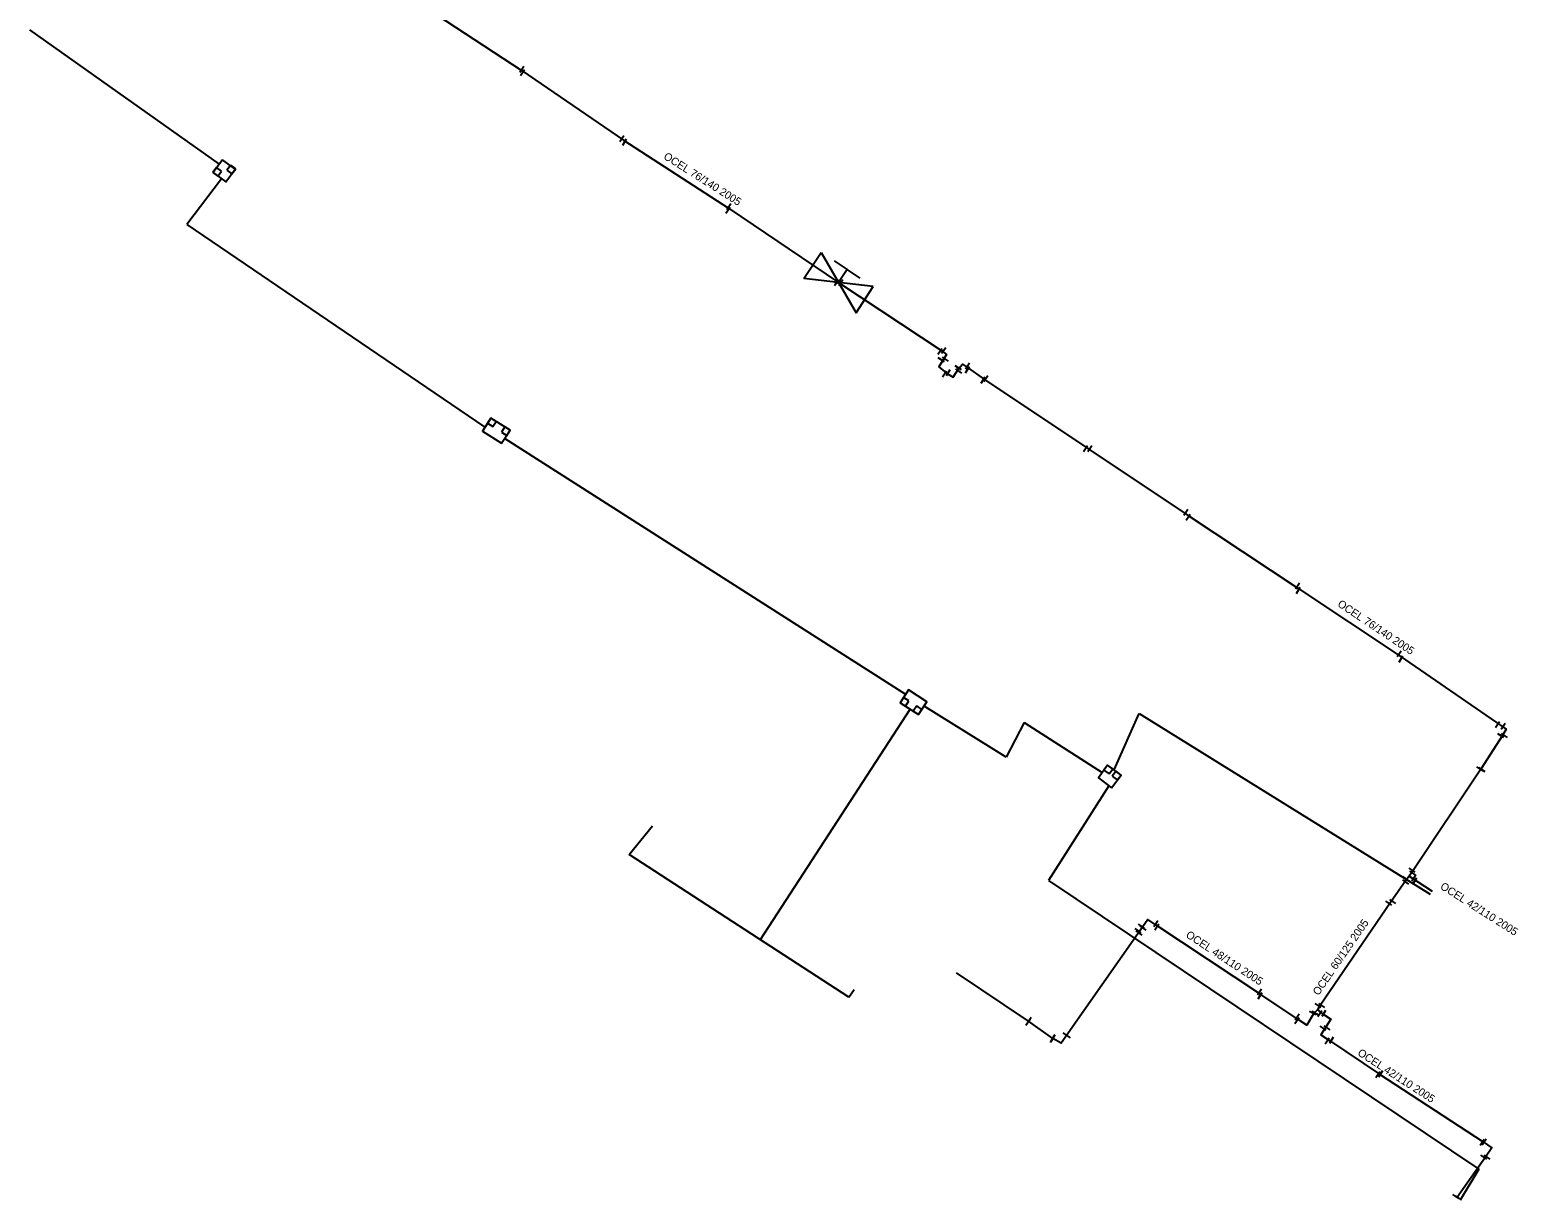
# Model space of a CAD drawing. Extents: x -642943 to -623314, y -1138561 to -1113539.
# Drawn here: x -641898.8 to -641755.6, y -1115757.5 to -1115644.8 of the extents above; entities that cross this region are included whole.
import ezdxf

# ---------------------------------------------------------------- set-up
doc = ezdxf.new("R2010")
doc.units = 0
for name, color, linetype in [('horkovod armatury', 7, 'Continuous'), ('horkovod dimenze', 7, 'Continuous'), ('horkovod předisol', 7, 'Continuous'), ('horkovod sváry', 7, 'Continuous'), ('horkovod trasa', 7, 'Continuous'), ('horkovod zrušený', 7, 'Continuous')]:
    doc.layers.add(name, color=color, linetype=linetype)

# ---------------------------------------------------------------- blocks, each defined once
blk = doc.blocks.new('POINT_DISPLAY')
blk.add_line((0, 0), (0, 0))
blk = doc.blocks.new('SPH')
at = {"layer": 'horkovod sváry'}
blk.add_line((0, -0.035), (0, 0.035), dxfattribs=at)
blk = doc.blocks.new('SCH_01_109')
at = {"layer": 'horkovod armatury'}
for p, q in [((10, 5), (-10, -5)), ((-10, -5), (-10, 5)), ((-10, 5), (10, -5)), ((-5, 5), (0, 5)), ((0, 5), (0, 0)), ((5, 5), (0, 5)), ((10, -5), (10, 5))]:
    blk.add_line(p, q, dxfattribs=at)

msp = doc.modelspace()

# ---------------------------------------------------------------- linework, layer by layer
at = {"layer": 'horkovod armatury'}
for centre in [(-641821.23, -1115669.14), (-641820.81, -1115669.13)]:
    msp.add_circle(centre, 0.1, dxfattribs=at)
at = {"layer": 'horkovod předisol'}
msp.add_line((-641766.14, -1115726.28), (-641763.92, -1115727.71), dxfattribs=at)
for points in [[(-641861.61, -1115642.13), (-641851.47, -1115648.76), (-641841.74, -1115655.44), (-641831.64, -1115661.98), (-641821.03, -1115669.13), (-641811.09, -1115675.72), (-641810.64, -1115676.08), (-641811.4, -1115677.26), (-641810.64, -1115677.87), (-641810.02, -1115678.26), (-641809.49, -1115677.46), (-641809.12, -1115677), (-641808.64, -1115677.33), (-641806.99, -1115678.46), (-641797.06, -1115685.12), (-641787.48, -1115691.5), (-641776.84, -1115698.54), (-641767.01, -1115705.11), (-641756.81, -1115712.13), (-641757.16, -1115712.74), (-641759.23, -1115715.98), (-641765.81, -1115725.84), (-641766.14, -1115726.28)], [(-641766.14, -1115726.28), (-641766.45, -1115726.68), (-641767.92, -1115728.82), (-641774.7, -1115738.71), (-641774.97, -1115739.14)], [(-641774.97, -1115739.14), (-641775.3, -1115739.47), (-641775.99, -1115740.62), (-641776.91, -1115740), (-641780.5, -1115737.6), (-641790.48, -1115730.99), (-641791.27, -1115730.45), (-641791.8, -1115731.18), (-641799.61, -1115742.36), (-641800.42, -1115741.89), (-641802.77, -1115740.22), (-641809.7, -1115735.57)], [(-641774.97, -1115739.14), (-641774.5, -1115739.49), (-641773.67, -1115740.05), (-641774.63, -1115741.54), (-641773.81, -1115742.08), (-641768.99, -1115745.33), (-641759.01, -1115751.86), (-641758.18, -1115752.44), (-641758.79, -1115753.32), (-641761.56, -1115757.24)]]:
    msp.add_lwpolyline(points, dxfattribs=at)
at = {"layer": 'horkovod trasa'}
msp.add_line((-641766.14, -1115726.28), (-641763.92, -1115727.71), dxfattribs=at)
for points in [[(-641861.61, -1115642.13), (-641851.47, -1115648.76), (-641841.74, -1115655.44), (-641831.64, -1115661.98), (-641821.03, -1115669.13), (-641811.09, -1115675.72), (-641810.64, -1115676.08), (-641811.4, -1115677.26), (-641810.64, -1115677.87), (-641810.02, -1115678.26), (-641809.49, -1115677.46), (-641809.12, -1115677), (-641808.64, -1115677.33), (-641806.99, -1115678.46), (-641797.06, -1115685.12), (-641787.48, -1115691.5), (-641776.84, -1115698.54), (-641767.01, -1115705.11), (-641756.81, -1115712.13), (-641757.16, -1115712.74), (-641759.23, -1115715.98), (-641765.81, -1115725.84), (-641766.14, -1115726.28)], [(-641766.14, -1115726.28), (-641766.45, -1115726.68), (-641767.92, -1115728.82), (-641774.7, -1115738.71), (-641774.97, -1115739.14)], [(-641774.97, -1115739.14), (-641775.3, -1115739.47), (-641775.99, -1115740.62), (-641776.91, -1115740), (-641780.5, -1115737.6), (-641790.48, -1115730.99), (-641791.27, -1115730.45), (-641791.8, -1115731.18), (-641799.61, -1115742.36), (-641800.42, -1115741.89), (-641802.77, -1115740.22), (-641809.7, -1115735.57)], [(-641774.97, -1115739.14), (-641774.5, -1115739.49), (-641773.67, -1115740.05), (-641774.63, -1115741.54), (-641773.81, -1115742.08), (-641768.99, -1115745.33), (-641759.01, -1115751.86), (-641758.18, -1115752.44), (-641758.79, -1115753.32), (-641761.56, -1115757.24)]]:
    msp.add_lwpolyline(points, dxfattribs=at)
at = {"layer": 'horkovod zrušený'}
for p, q in [((-641880.6, -1115657.73), (-641898.85, -1115644.81)), ((-641880.87, -1115658.07), (-641881.23, -1115658.55)), ((-641880.39, -1115658.43), (-641880.87, -1115658.07)), ((-641879.52, -1115657.85), (-641879.88, -1115658.33)), ((-641879.04, -1115658.21), (-641879.52, -1115657.85)), ((-641879.4, -1115658.69), (-641879.04, -1115658.21)), ((-641880.39, -1115659.15), (-641883.75, -1115663.55)), ((-641881.23, -1115658.55), (-641880.75, -1115658.91)), ((-641880.75, -1115658.91), (-641880.39, -1115658.43)), ((-641879.88, -1115658.33), (-641879.4, -1115658.69)), ((-641883.75, -1115663.55), (-641855.06, -1115683.07)), ((-641854.49, -1115682.19), (-641854.81, -1115682.69)), ((-641853.99, -1115682.51), (-641854.49, -1115682.19)), ((-641854.31, -1115683.01), (-641853.99, -1115682.51)), ((-641854.81, -1115682.69), (-641854.31, -1115683.01)), ((-641853.13, -1115683.03), (-641853.46, -1115683.53)), ((-641853.46, -1115683.53), (-641852.96, -1115683.86)), ((-641852.63, -1115683.36), (-641853.13, -1115683.03)), ((-641852.96, -1115683.86), (-641852.63, -1115683.36)), ((-641853.15, -1115684.15), (-641814.58, -1115708.77)), ((-641814.78, -1115709.08), (-641815.1, -1115709.58)), ((-641815.1, -1115709.58), (-641814.6, -1115709.9)), ((-641814.28, -1115709.4), (-641814.78, -1115709.08)), ((-641814.6, -1115709.9), (-641814.28, -1115709.4)), ((-641828.55, -1115732.36), (-641814.16, -1115710.19)), ((-641813.51, -1115709.88), (-641813.85, -1115710.38)), ((-641813.85, -1115710.38), (-641813.35, -1115710.72)), ((-641813.01, -1115710.22), (-641813.51, -1115709.88)), ((-641813.35, -1115710.72), (-641813.01, -1115710.22)), ((-641804.92, -1115714.83), (-641812.8, -1115709.92)), ((-641794.52, -1115716.05), (-641792.12, -1115710.63)), ((-641792.12, -1115710.63), (-641764.11, -1115728.01)), ((-641803.17, -1115711.47), (-641804.92, -1115714.83)), ((-641803.17, -1115711.47), (-641795.66, -1115716.29)), ((-641795.15, -1115715.58), (-641795.5, -1115716.07)), ((-641794.66, -1115715.93), (-641795.15, -1115715.58)), ((-641795.5, -1115716.07), (-641795.01, -1115716.42)), ((-641795.01, -1115716.42), (-641794.66, -1115715.93)), ((-641794.34, -1115716.18), (-641794.7, -1115716.66)), ((-641794.7, -1115716.66), (-641794.22, -1115717.02)), ((-641793.86, -1115716.54), (-641794.34, -1115716.18)), ((-641794.22, -1115717.02), (-641793.86, -1115716.54)), ((-641795.02, -1115717.57), (-641800.85, -1115726.7)), ((-641841.18, -1115724.18), (-641838.94, -1115721.43)), ((-641820.06, -1115737.92), (-641841.18, -1115724.18)), ((-641800.85, -1115726.7), (-641759.44, -1115754.47)), ((-641820.06, -1115737.92), (-641819.55, -1115737.17)), ((-641759.44, -1115754.47), (-641761.23, -1115757.47))]:
    msp.add_line(p, q, dxfattribs=at)
for points in [[(-641880.3, -1115657.32), (-641881.2, -1115658.54), (-641879.98, -1115659.44), (-641879.08, -1115658.22), (-641880.3, -1115657.32)], [(-641853.45, -1115684.61), (-641852.63, -1115683.36), (-641854.49, -1115682.19), (-641855.3, -1115683.45), (-641853.45, -1115684.61)], [(-641813.35, -1115710.72), (-641812.53, -1115709.5), (-641814.31, -1115708.34), (-641815.1, -1115709.58), (-641813.35, -1115710.72)], [(-641794.76, -1115717.76), (-641793.86, -1115716.54), (-641795.15, -1115715.58), (-641796.03, -1115716.82), (-641794.76, -1115717.76)]]:
    msp.add_lwpolyline(points, dxfattribs=at)

# ---------------------------------------------------------------- block references
at = {"layer": 'horkovod armatury', "xscale": 0.29998715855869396, "yscale": 0.29998715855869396, "rotation": -33.22654402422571}
msp.add_blockref('SCH_01_109', (-641821.03, -1115669.14), dxfattribs=at)
at = {"layer": 'horkovod sváry'}
for p, xscale, yscale, rotation in [((-641851.51, -1115648.59), 10.000007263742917, 10.000007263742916, -33.51809530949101), ((-641851.45, -1115648.91), 10.00001724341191, 10.00001724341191, -33.85634168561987), ((-641841.89, -1115655.27), 10.00001054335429, 10.000010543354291, -32.200241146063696), ((-641841.61, -1115655.61), 9.99998342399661, 9.999983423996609, -32.147383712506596), ((-641831.67, -1115662.18), 9.999983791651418, 9.99998379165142, -34.07715628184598), ((-641831.59, -1115661.81), 10.000012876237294, 10.000012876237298, -35.38539210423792), ((-641821.24, -1115669.14), 10.000012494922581, 10.00001249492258, -34.52339088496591), ((-641820.82, -1115669.14), 9.999999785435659, 9.999999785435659, -33.359219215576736), ((-641811.27, -1115675.75), 10.000007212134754, 10.000007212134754, -38.17553854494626), ((-641810.92, -1115675.66), 10.000021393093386, 10.000021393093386, -37.53478850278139), ((-641811.15, -1115676.58), 9.99999480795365, 9.999994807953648, 57.46201646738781), ((-641810.74, -1115676.51), 9.999986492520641, 9.999986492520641, 56.18369107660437), ((-641808.64, -1115677.16), 10.000012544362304, 10.000012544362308, -33.931894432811), ((-641810.84, -1115677.92), 10.000023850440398, 10.000023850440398, -32.943257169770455), ((-641810.47, -1115677.8), 9.999988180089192, 9.999988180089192, -32.02990307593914), ((-641809.54, -1115677.31), 9.999987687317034, 9.999987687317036, -122.76933973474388), ((-641809.49, -1115677.65), 10.000005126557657, 10.000005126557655, -124.15344978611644), ((-641808.63, -1115677.52), 9.999999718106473, 9.999999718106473, -32.55885576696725), ((-641807.13, -1115678.52), 10.000016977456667, 10.000016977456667, -33.998789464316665), ((-641806.88, -1115678.38), 9.999996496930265, 9.999996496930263, -33.47110590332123), ((-641797.27, -1115685.12), 10.000029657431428, 10.000029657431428, -33.31918648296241), ((-641796.87, -1115685.12), 10.000002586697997, 10.000002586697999, -33.65743427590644), ((-641787.63, -1115691.25), 9.999989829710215, 9.999989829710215, -33.65588026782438), ((-641787.41, -1115691.72), 9.99999135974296, 9.999991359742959, -32.31104860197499), ((-641776.88, -1115698.32), 9.999999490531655, 9.999999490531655, -34.73549977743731), ((-641776.8, -1115698.76), 10.000017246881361, 10.00001724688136, -32.75431885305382), ((-641767.1, -1115704.86), 9.999986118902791, 9.999986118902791, -35.101286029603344), ((-641766.92, -1115705.38), 10.00001880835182, 10.000018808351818, -32.22133888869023), ((-641757.65, -1115711.67), 9.999995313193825, 9.999995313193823, -33.83747240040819), ((-641757.32, -1115712.75), 10.000006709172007, 10.000006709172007, 58.872754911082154), ((-641757.09, -1115711.84), 10.000030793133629, 10.000030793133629, -34.134652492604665), ((-641756.97, -1115712.73), 10.0000124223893, 10.0000124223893, 56.84598341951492), ((-641759.34, -1115715.94), 10.000010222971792, 10.000010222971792, 58.521474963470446), ((-641759.13, -1115716.04), 10.000013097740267, 10.000013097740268, 56.81379283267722), ((-641765.85, -1115725.7), 9.9999780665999, 9.9999780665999, 58.05530848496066), ((-641766.46, -1115726.52), 10.000013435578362, 10.000013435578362, 55.83175045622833), ((-641766.45, -1115726.84), 10.000012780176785, 10.000012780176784, 56.182507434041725), ((-641765.78, -1115725.99), 9.999988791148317, 9.999988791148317, 56.61613930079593), ((-641765.7, -1115726.43), 9.999999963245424, 9.999999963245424, -32.72900634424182), ((-641765.6, -1115726.74), 10.000012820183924, 10.000012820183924, -33.40006726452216), ((-641768.09, -1115728.88), 10.000000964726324, 10.000000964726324, 56.30985847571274), ((-641767.72, -1115728.71), 9.999984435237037, 9.999984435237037, 55.8429232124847), ((-641792.21, -1115731.52), 9.999978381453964, 9.999978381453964, 54.246112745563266), ((-641791.88, -1115731.08), 10.000023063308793, 10.000023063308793, 56.509801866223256), ((-641791.74, -1115731.27), 10.000007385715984, 10.000007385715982, 55.22231473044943), ((-641790.52, -1115730.84), 9.999986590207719, 9.999986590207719, -33.603341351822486), ((-641790.41, -1115731.15), 9.999977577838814, 9.999977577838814, -33.15956483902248), ((-641792.11, -1115731.76), 9.999995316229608, 9.999995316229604, 53.69125527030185), ((-641780.54, -1115737.41), 10.000000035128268, 10.000000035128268, -34.04585370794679), ((-641780.48, -1115737.78), 10.000000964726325, 10.000000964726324, -33.6901415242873), ((-641802.7, -1115740.15), 9.999975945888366, 9.999975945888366, -34.97619533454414), ((-641776.93, -1115740.18), 10.00001058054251, 10.00001058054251, -34.157297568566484), ((-641776.92, -1115739.81), 10.000002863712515, 10.000002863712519, -33.98339804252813), ((-641775.43, -1115739.47), 9.99997188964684, 9.99997188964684, 61.2573295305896), ((-641775.2, -1115739.45), 10.000009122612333, 10.000009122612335, -119.71079548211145), ((-641774.88, -1115738.73), 9.999980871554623, 9.999980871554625, 55.7935642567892), ((-641774.72, -1115739.5), 9.999970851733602, 9.999970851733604, -34.04274674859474), ((-641774.54, -1115738.73), 10.000023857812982, 10.00002385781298, 55.81598878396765), ((-641774.34, -1115739.46), 9.999991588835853, 9.999991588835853, -31.281080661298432), ((-641802.81, -1115740.32), 10.000009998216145, 10.000009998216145, -35.797494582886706), ((-641799.13, -1115741.54), 9.999991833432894, 9.999991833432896, 55.55453517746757), ((-641774.41, -1115740.91), 10.00000104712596, 10.000001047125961, 56.920800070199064), ((-641774.03, -1115740.87), 9.999986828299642, 9.999986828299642, 55.14911396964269), ((-641800.47, -1115741.97), 9.999988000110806, 9.999988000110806, -27.614519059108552), ((-641800.37, -1115741.82), 10.000021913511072, 10.000021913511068, -28.072455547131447), ((-641799.01, -1115741.65), 9.999985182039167, 9.999985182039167, 55.45706913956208), ((-641774.02, -1115742.13), 10.000003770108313, 10.000003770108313, -34.15248783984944), ((-641773.6, -1115742.04), 10.000003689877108, 10.000003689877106, -30.74993537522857), ((-641769.14, -1115745.37), 10.000008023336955, 10.000008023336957, -32.775928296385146), ((-641768.86, -1115745.29), 9.999983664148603, 9.999983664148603, -31.94121294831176), ((-641759.11, -1115751.88), 10.000008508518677, 10.000008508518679, -34.556768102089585), ((-641758.93, -1115751.84), 10.000005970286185, 10.000005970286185, -34.55580623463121), ((-641758.95, -1115753.32), 9.999980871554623, 9.999980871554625, 55.7935642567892), ((-641758.64, -1115753.32), 9.999993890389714, 9.999993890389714, 54.92417808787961), ((-641761.65, -1115757.11), 10.000005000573, 10.000005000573, 54.566782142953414), ((-641761.4, -1115757.24), 10.000005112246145, 10.000005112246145, 55.24666420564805)]:
    msp.add_blockref('SPH', p, dxfattribs=dict(at, xscale=xscale, yscale=yscale, rotation=rotation))
at = {"layer": 'horkovod zrušený'}
for p in [(-641879.46, -1115658.27), (-641880.81, -1115658.49), (-641854.4, -1115682.6), (-641853.04, -1115683.44), (-641814.69, -1115709.49), (-641813.43, -1115710.3), (-641813.43, -1115710.3), (-641795.08, -1115716), (-641794.28, -1115716.6)]:
    msp.add_blockref('POINT_DISPLAY', p, dxfattribs=at)

# ---------------------------------------------------------------- texts
at = {"layer": 'horkovod dimenze'}
for s, rotation, p in [('OCEL 76/140 2005', 327.5864, (-641837.94, -1115657.18)), ('OCEL 76/140 2005', 326.2289, (-641773.1, -1115700.24)), ('OCEL 42/110 2005', 327.5128, (-641763.22, -1115727.44)), ('OCEL 60/125 2005', 55.4199, (-641774.86, -1115737.82)), ('OCEL 48/110 2005', 326.6424, (-641787.69, -1115732.1)), ('OCEL 42/110 2005', 327.0143, (-641771.17, -1115743.46))]:
    msp.add_text(s, height=0.75, rotation=rotation, dxfattribs=at).set_placement(p)

doc.saveas('drawing.dxf')
